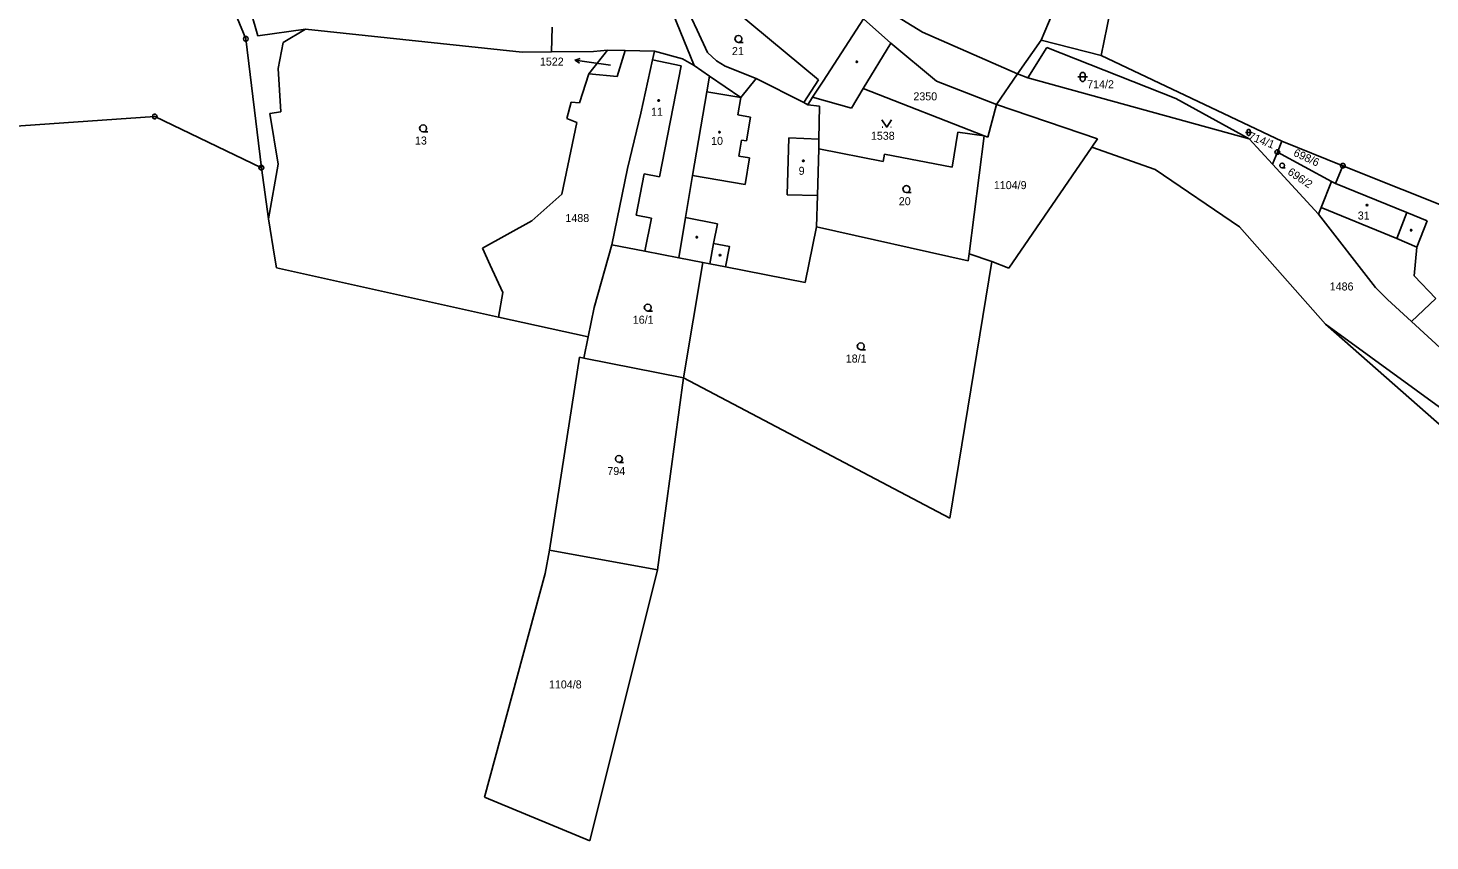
# Model space of a CAD drawing. Extents: x -852001 to -848657, y -1054973 to -1052182.
# Drawn here: x -850781 to -850483.1, y -1053765.9 to -1053593.3 of the extents above; entities that cross this region are included whole.
import ezdxf

# ---------------------------------------------------------------- set-up
doc = ezdxf.new("R2010")
doc.units = 0
for name, color, linetype in [('KN_HRANICE', 7, 'Continuous'), ('KN_KULTURY', 7, 'Continuous'), ('KN_MEZNIKY', 7, 'Continuous'), ('KN_PARCELY', 7, 'Continuous'), ('KN_SLUCKY', 7, 'Continuous'), ('KN_STAVEBNI', 7, 'Continuous')]:
    doc.layers.add(name, color=color, linetype=linetype)

# ---------------------------------------------------------------- blocks, each defined once
blk = doc.blocks.new('304')
blk.add_lwpolyline([(0, 0), (-0.38, 0.1), (-0.65, 0.37), (-0.75, 0.74), (-0.65, 1.11), (-0.38, 1.38), (-0.01, 1.48), (0.36, 1.38), (0.63, 1.11), (0.73, 0.73), (0.63, 0.35), (0.36, 0.08), (-0.02, -0.02), (0.98, -0.02)])
blk = doc.blocks.new('314')
for p, q in [((-0.95, 0), (-0.85, 0)), ((0.85, 0), (0.95, 0))]:
    blk.add_line(p, q)
blk.add_lwpolyline([(-1, 1.5), (0, 0), (1, 1.5)])
blk = doc.blocks.new('316')
for points in [[(-1, 1), (0.27, 1), (1, 1)], [(-0.5, 1.5), (-0.4, 1.79), (-0.15, 1.97), (0.16, 1.97), (0.41, 1.79), (0.51, 1.5), (0.51, 0.5), (0.41, 0.21), (0.16, 0.03), (-0.15, 0.03), (-0.4, 0.21), (-0.5, 0.5), (-0.5, 1.5)]]:
    blk.add_lwpolyline(points)
blk = doc.blocks.new('10292')
blk.add_line((0, 3), (0, 0))
blk.add_lwpolyline([(-0.5, 2), (0, 3), (0.5, 2)])
blk = doc.blocks.new('402')
blk.add_lwpolyline([(0.09, 0.15), (0.18, 0), (0.09, -0.15), (-0.09, -0.15), (-0.18, 0), (-0.09, 0.15), (0.09, 0.15)])
blk = doc.blocks.new('105')
blk.add_line((-0.12, 0), (0.12, 0))
blk.add_lwpolyline([(0.15, 0.48), (0.4, 0.3), (0.5, 0.01), (0.4, -0.28), (0.15, -0.46), (-0.16, -0.46), (-0.41, -0.28), (-0.51, 0.01), (-0.41, 0.3), (-0.16, 0.48), (0.15, 0.48)])

msp = doc.modelspace()

# ---------------------------------------------------------------- linework, layer by layer
at = {"layer": 'KN_HRANICE'}
for p, q in [((-850545.42, -1053562.28), (-850552.92, -1053599.08)), ((-850646.41, -1053584.08), (-850639.44, -1053601.2)), ((-850738.81, -1053585.42), (-850734.66, -1053595.56)), ((-850635.17, -1053585.8), (-850612.97, -1053604.25)), ((-850565.66, -1053595.86), (-850561.72, -1053586.38)), ((-850733.6, -1053589.76), (-850732.16, -1053594.91)), ((-850600.56, -1053588.2), (-850590.91, -1053594.16)), ((-850722.02, -1053593.47), (-850732.16, -1053594.91)), ((-850726.71, -1053596.35), (-850722.02, -1053593.47)), ((-850722.02, -1053593.47), (-850675.99, -1053598.41)), ((-850669.55, -1053593.05), (-850669.76, -1053598.34)), ((-850639.95, -1053591.18), (-850638.77, -1053593.71)), ((-850638.77, -1053593.71), (-850636.55, -1053598.46)), ((-850597.64, -1053596.49), (-850603.43, -1053591.33)), ((-850734.66, -1053595.56), (-850731.37, -1053622.93)), ((-850727.84, -1053601.86), (-850726.71, -1053596.35)), ((-850597.64, -1053596.49), (-850603.51, -1053606.11)), ((-850587.92, -1053604.52), (-850597.64, -1053596.49)), ((-850590.91, -1053594.16), (-850570.67, -1053603.01)), ((-850570.67, -1053603.01), (-850565.66, -1053595.86)), ((-850565.66, -1053595.86), (-850552.92, -1053599.08)), ((-850675.99, -1053598.41), (-850669.76, -1053598.34)), ((-850669.76, -1053598.34), (-850660.81, -1053598.24)), ((-850661.81, -1053603.01), (-850657.8, -1053597.97)), ((-850660.81, -1053598.24), (-850657.8, -1053597.97)), ((-850657.8, -1053597.97), (-850654.08, -1053598.05)), ((-850655.76, -1053603.54), (-850654.08, -1053598.05)), ((-850654.08, -1053598.05), (-850647.82, -1053598.17)), ((-850650.71, -1053611.35), (-850648.23, -1053600.03)), ((-850648.23, -1053600.03), (-850647.82, -1053598.17)), ((-850647.82, -1053598.17), (-850641.87, -1053599.8)), ((-850641.87, -1053599.8), (-850639.44, -1053601.2)), ((-850636.55, -1053598.46), (-850634.65, -1053600.2)), ((-850568.53, -1053603.83), (-850564.48, -1053597.38)), ((-850564.48, -1053597.38), (-850537.04, -1053608.24)), ((-850514.55, -1053617.3), (-850552.92, -1053599.08)), ((-850727.27, -1053611.05), (-850727.84, -1053601.86)), ((-850663.74, -1053609.12), (-850661.81, -1053603.01)), ((-850661.81, -1053603.01), (-850655.76, -1053603.54)), ((-850636.16, -1053603.46), (-850639.44, -1053601.2)), ((-850634.65, -1053600.2), (-850632.83, -1053601.39)), ((-850632.83, -1053601.39), (-850626.23, -1053603.99)), ((-850575.2, -1053609.48), (-850570.67, -1053603.01)), ((-850568.53, -1053603.83), (-850570.67, -1053603.01)), ((-850636.73, -1053606.84), (-850636.16, -1053603.46)), ((-850629.52, -1053608.02), (-850636.16, -1053603.46)), ((-850629.52, -1053608.02), (-850626.23, -1053603.99)), ((-850626.23, -1053603.99), (-850616.11, -1053609.04)), ((-850612.97, -1053604.25), (-850616.11, -1053609.04)), ((-850575.2, -1053609.48), (-850587.92, -1053604.52)), ((-850521.46, -1053616.8), (-850568.53, -1053603.83)), ((-850666.46, -1053612.48), (-850665.53, -1053608.97)), ((-850665.53, -1053608.97), (-850663.74, -1053609.12)), ((-850639.73, -1053624.59), (-850636.73, -1053606.84)), ((-850616.11, -1053609.04), (-850615.28, -1053609.57)), ((-850614.24, -1053607.97), (-850615.28, -1053609.57)), ((-850605.98, -1053610.26), (-850614.24, -1053607.97)), ((-850603.51, -1053606.11), (-850605.98, -1053610.26)), ((-850603.51, -1053606.11), (-850577.79, -1053616.12)), ((-850537.04, -1053608.24), (-850521.46, -1053616.8)), ((-850727.27, -1053611.05), (-850729.55, -1053611.4)), ((-850729.55, -1053611.4), (-850727.84, -1053622.2)), ((-850653.56, -1053623.08), (-850650.71, -1053611.35)), ((-850615.28, -1053609.57), (-850612.79, -1053609.83)), ((-850612.9, -1053616.89), (-850612.79, -1053609.83)), ((-850576.99, -1053616.43), (-850575.2, -1053609.48)), ((-850553.68, -1053616.8), (-850575.2, -1053609.48)), ((-850754.03, -1053612.06), (-850790.19, -1053614.59)), ((-850731.37, -1053622.93), (-850754.03, -1053612.06)), ((-850667.53, -1053628.53), (-850664.31, -1053613.34)), ((-850664.31, -1053613.34), (-850666.46, -1053612.48)), ((-850619.29, -1053616.58), (-850619.67, -1053628.68)), ((-850612.9, -1053616.89), (-850619.29, -1053616.58)), ((-850612.93, -1053618.93), (-850612.9, -1053616.89)), ((-850583.4, -1053615.39), (-850584.6, -1053622.84)), ((-850577.79, -1053616.12), (-850583.4, -1053615.39)), ((-850580.98, -1053641.2), (-850577.79, -1053616.12)), ((-850577.79, -1053616.12), (-850576.99, -1053616.43)), ((-850554.91, -1053618.59), (-850553.68, -1053616.8)), ((-850516.5, -1053622.17), (-850521.46, -1053616.8)), ((-850514.55, -1053617.3), (-850515.48, -1053619.62)), ((-850514.55, -1053617.3), (-850501.57, -1053622.5)), ((-850612.93, -1053618.93), (-850613.21, -1053628.86)), ((-850599.25, -1053621.58), (-850612.93, -1053618.93)), ((-850599, -1053620.06), (-850599.25, -1053621.58)), ((-850584.6, -1053622.84), (-850599, -1053620.06)), ((-850572.54, -1053644.27), (-850554.91, -1053618.59)), ((-850541.46, -1053623.3), (-850554.91, -1053618.59)), ((-850515.48, -1053619.62), (-850516.5, -1053622.17)), ((-850515.48, -1053619.62), (-850503.95, -1053625.86)), ((-850731.37, -1053622.93), (-850729.84, -1053633.77)), ((-850727.84, -1053622.2), (-850729.84, -1053633.77)), ((-850656.92, -1053639.28), (-850653.56, -1053623.08)), ((-850523.5, -1053635.48), (-850541.46, -1053623.3)), ((-850516.5, -1053622.17), (-850506.73, -1053632.76)), ((-850501.57, -1053622.5), (-850503.12, -1053626.3)), ((-850501.57, -1053622.5), (-850462.18, -1053638.28)), ((-850641.24, -1053633.53), (-850639.73, -1053624.59)), ((-850506.18, -1053631.4), (-850503.95, -1053625.86)), ((-850503.95, -1053625.86), (-850503.12, -1053626.3)), ((-850503.12, -1053626.3), (-850487.95, -1053632.45)), ((-850673.91, -1053634.19), (-850667.53, -1053628.53)), ((-850619.67, -1053628.68), (-850613.21, -1053628.86)), ((-850613.21, -1053628.86), (-850613.39, -1053635.48)), ((-850506.73, -1053632.76), (-850506.18, -1053631.4)), ((-850494.64, -1053648.37), (-850506.73, -1053632.76)), ((-850483.67, -1053634.23), (-850487.95, -1053632.45)), ((-850729.84, -1053633.77), (-850728.5, -1053642.15)), ((-850684.37, -1053639.99), (-850673.91, -1053634.19)), ((-850642.68, -1053642.07), (-850641.24, -1053633.53)), ((-850615.84, -1053647.32), (-850613.39, -1053635.48)), ((-850613.39, -1053635.48), (-850581.18, -1053642.71)), ((-850505.26, -1053656.14), (-850523.5, -1053635.48)), ((-850483.67, -1053634.23), (-850485.83, -1053639.78)), ((-850682.73, -1053643.61), (-850684.37, -1053639.99)), ((-850660.67, -1053652.62), (-850656.92, -1053639.28)), ((-850656.92, -1053639.28), (-850649.89, -1053640.66)), ((-850649.89, -1053640.66), (-850642.68, -1053642.07)), ((-850581.18, -1053642.71), (-850580.98, -1053641.2)), ((-850580.98, -1053641.2), (-850576.19, -1053642.88)), ((-850485.83, -1053639.78), (-850486.44, -1053645.86)), ((-850728.5, -1053642.15), (-850728.18, -1053644.2)), ((-850728.18, -1053644.2), (-850680.97, -1053654.64)), ((-850682.73, -1053643.61), (-850680.1, -1053649.45)), ((-850642.68, -1053642.07), (-850637.57, -1053643.07)), ((-850641.71, -1053667.54), (-850637.57, -1053643.07)), ((-850637.57, -1053643.07), (-850636.11, -1053643.35)), ((-850636.11, -1053643.35), (-850632.74, -1053644.01)), ((-850632.74, -1053644.01), (-850615.84, -1053647.32)), ((-850585.08, -1053697.36), (-850576.19, -1053642.88)), ((-850576.19, -1053642.88), (-850572.54, -1053644.27)), ((-850486.44, -1053645.86), (-850481.82, -1053650.71)), ((-850680.1, -1053649.45), (-850680.97, -1053654.64)), ((-850492.05, -1053650.95), (-850494.64, -1053648.37)), ((-850486.95, -1053655.61), (-850481.82, -1053650.71)), ((-850661.92, -1053658.86), (-850660.67, -1053652.62)), ((-850492.05, -1053650.95), (-850486.95, -1053655.61)), ((-850661.92, -1053658.86), (-850680.97, -1053654.64)), ((-850456.22, -1053699.36), (-850505.26, -1053656.14)), ((-850505.26, -1053656.14), (-850454.26, -1053693.33)), ((-850476.59, -1053665.13), (-850486.95, -1053655.61)), ((-850662.83, -1053663.39), (-850661.92, -1053658.86)), ((-850670.18, -1053704.16), (-850663.78, -1053663.19)), ((-850663.78, -1053663.19), (-850662.83, -1053663.39)), ((-850641.71, -1053667.54), (-850662.83, -1053663.39)), ((-850647.22, -1053708.36), (-850641.71, -1053667.54)), ((-850641.71, -1053667.54), (-850585.08, -1053697.36)), ((-850671.08, -1053709.08), (-850670.18, -1053704.16)), ((-850647.22, -1053708.36), (-850670.18, -1053704.16)), ((-850683.99, -1053756.59), (-850671.08, -1053709.08)), ((-850661.58, -1053765.92), (-850647.22, -1053708.36)), ((-850661.58, -1053765.92), (-850683.99, -1053756.59))]:
    msp.add_line(p, q, dxfattribs=at)
at = {"layer": 'KN_PARCELY'}
msp.add_line((-850657.18, -1053601.12), (-850661.75, -1053600.48), dxfattribs=at)
at = {"layer": 'KN_SLUCKY'}
for p, q in [((-850603.43, -1053591.33), (-850612.02, -1053604.55)), ((-850648.23, -1053600.03), (-850642.17, -1053601.32)), ((-850646.79, -1053624.87), (-850642.17, -1053601.32)), ((-850612.02, -1053604.55), (-850614.24, -1053607.97)), ((-850636.73, -1053606.84), (-850629.52, -1053608.02)), ((-850629.52, -1053608.02), (-850630.13, -1053611.69)), ((-850627.43, -1053612.17), (-850630.13, -1053611.69)), ((-850627.43, -1053612.17), (-850628.28, -1053617.21)), ((-850629.33, -1053617.04), (-850629.9, -1053620.46)), ((-850628.28, -1053617.21), (-850629.33, -1053617.04)), ((-850629.9, -1053620.46), (-850627.64, -1053620.84)), ((-850627.64, -1053620.84), (-850628.59, -1053626.47)), ((-850651.76, -1053632.99), (-850650.04, -1053624.23)), ((-850650.04, -1053624.23), (-850646.79, -1053624.87)), ((-850628.59, -1053626.47), (-850639.73, -1053624.59)), ((-850490.11, -1053637.94), (-850506.18, -1053631.4)), ((-850490.11, -1053637.94), (-850487.95, -1053632.45)), ((-850648.51, -1053633.63), (-850651.76, -1053632.99)), ((-850649.89, -1053640.66), (-850648.51, -1053633.63)), ((-850641.24, -1053633.53), (-850634.45, -1053634.86)), ((-850634.45, -1053634.86), (-850635.27, -1053639.02)), ((-850485.83, -1053639.78), (-850490.11, -1053637.94)), ((-850635.27, -1053639.02), (-850636.11, -1053643.35))]:
    msp.add_line(p, q, dxfattribs=at)
msp.add_lwpolyline([(-850635.27, -1053639.02), (-850631.89, -1053639.68), (-850632.74, -1053644.01)], dxfattribs=at)
at = {"layer": 'KN_STAVEBNI'}
for p, q in [((-850650.71, -1053611.35), (-850648.23, -1053600.03)), ((-850648.23, -1053600.03), (-850642.17, -1053601.32)), ((-850646.79, -1053624.87), (-850642.17, -1053601.32)), ((-850639.73, -1053624.59), (-850636.73, -1053606.84)), ((-850636.73, -1053606.84), (-850629.52, -1053608.02)), ((-850629.52, -1053608.02), (-850630.13, -1053611.69)), ((-850653.56, -1053623.08), (-850650.71, -1053611.35)), ((-850627.43, -1053612.17), (-850630.13, -1053611.69)), ((-850627.43, -1053612.17), (-850628.28, -1053617.21)), ((-850629.33, -1053617.04), (-850629.9, -1053620.46)), ((-850628.28, -1053617.21), (-850629.33, -1053617.04)), ((-850619.29, -1053616.58), (-850619.67, -1053628.68)), ((-850612.9, -1053616.89), (-850619.29, -1053616.58)), ((-850612.93, -1053618.93), (-850612.9, -1053616.89)), ((-850629.9, -1053620.46), (-850627.64, -1053620.84)), ((-850627.64, -1053620.84), (-850628.59, -1053626.47)), ((-850612.93, -1053618.93), (-850613.21, -1053628.86)), ((-850656.92, -1053639.28), (-850653.56, -1053623.08)), ((-850651.76, -1053632.99), (-850650.04, -1053624.23)), ((-850650.04, -1053624.23), (-850646.79, -1053624.87)), ((-850628.59, -1053626.47), (-850639.73, -1053624.59)), ((-850506.18, -1053631.4), (-850503.95, -1053625.86)), ((-850503.95, -1053625.86), (-850503.12, -1053626.3)), ((-850503.12, -1053626.3), (-850487.95, -1053632.45)), ((-850619.67, -1053628.68), (-850613.21, -1053628.86)), ((-850490.11, -1053637.94), (-850506.18, -1053631.4)), ((-850490.11, -1053637.94), (-850487.95, -1053632.45)), ((-850648.51, -1053633.63), (-850651.76, -1053632.99)), ((-850649.89, -1053640.66), (-850648.51, -1053633.63)), ((-850656.92, -1053639.28), (-850649.89, -1053640.66))]:
    msp.add_line(p, q, dxfattribs=at)

# ---------------------------------------------------------------- block references
at = {"layer": 'KN_KULTURY'}
for name, p in [('304', (-850630, -1053596.3)), ('402', (-850604.84, -1053600.42)), ('316', (-850556.86, -1053604.64)), ('402', (-850646.96, -1053608.67)), ('304', (-850697, -1053615.3)), ('314', (-850598.5, -1053614.29)), ('402', (-850634.01, -1053615.36)), ('402', (-850616.21, -1053621.49)), ('304', (-850594.31, -1053628.19)), ('402', (-850496.44, -1053630.87)), ('402', (-850638.84, -1053637.68)), ('402', (-850487.05, -1053636.19)), ('402', (-850633.91, -1053641.51)), ('304', (-850649.25, -1053653.36)), ('304', (-850604, -1053661.6)), ('304', (-850655.39, -1053685.5))]:
    msp.add_blockref(name, p, dxfattribs=at)
at = {"layer": 'KN_KULTURY', "xscale": 0.67, "yscale": 0.67}
for name, p in [('316', (-850521.58, -1053616.1)), ('304', (-850514.47, -1053622.95))]:
    msp.add_blockref(name, p, dxfattribs=at)
at = {"layer": 'KN_MEZNIKY'}
for p in [(-850734.66, -1053595.56), (-850754.03, -1053612.06), (-850515.48, -1053619.62), (-850731.37, -1053622.93), (-850501.57, -1053622.5)]:
    msp.add_blockref('105', p, dxfattribs=at)
at = {"layer": 'KN_PARCELY', "rotation": 81.99025999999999}
msp.add_blockref('10292', (-850661.75, -1053600.48), dxfattribs=at)

# ---------------------------------------------------------------- texts
at = {"layer": 'KN_PARCELY'}
for s, height, p in [('1522', 1.7, (-850672.19, -1053601.23)), ('21', 1.7, (-850631.38, -1053599)), ('1522', 0.1, (-850657.38, -1053601.12)), ('714/2', 1.7, (-850555.9, -1053606.04)), ('2350', 1.7, (-850592.83, -1053608.62)), ('11', 1.7, (-850648.57, -1053611.89)), ('13', 1.7, (-850698.74, -1053618)), ('10', 1.7, (-850635.81, -1053618.07)), ('1538', 1.7, (-850601.86, -1053616.99)), ('9', 1.7, (-850617.21, -1053624.43)), ('1104/9', 1.7, (-850575.73, -1053627.47)), ('20', 1.7, (-850595.93, -1053630.89)), ('1488', 1.7, (-850666.77, -1053634.46)), ('31', 1.7, (-850498.4, -1053633.93)), ('1486', 1.7, (-850504.36, -1053649)), ('16/1', 1.7, (-850652.45, -1053656.06)), ('18/1', 1.7, (-850607.2, -1053664.3)), ('794', 1.7, (-850657.86, -1053688.2)), ('1104/8', 1.7, (-850670.27, -1053733.53))]:
    msp.add_text(s, height=height, dxfattribs=at).set_placement(p)
for s, rotation, p in [('714/1', 338.618, (-850521.79, -1053616.84)), ('698/6', 335.066, (-850512.22, -1053620.33)), ('696/2', 325.841, (-850513.46, -1053624.2))]:
    msp.add_text(s, height=1.7, rotation=rotation, dxfattribs=at).set_placement(p)

doc.saveas('drawing.dxf')
